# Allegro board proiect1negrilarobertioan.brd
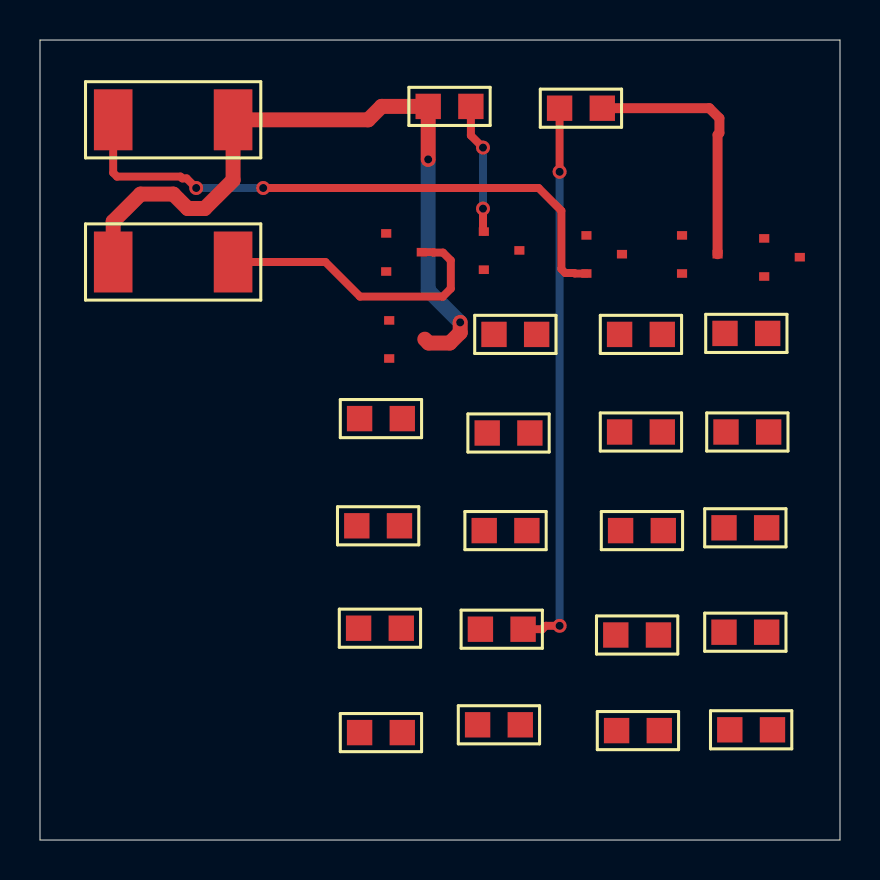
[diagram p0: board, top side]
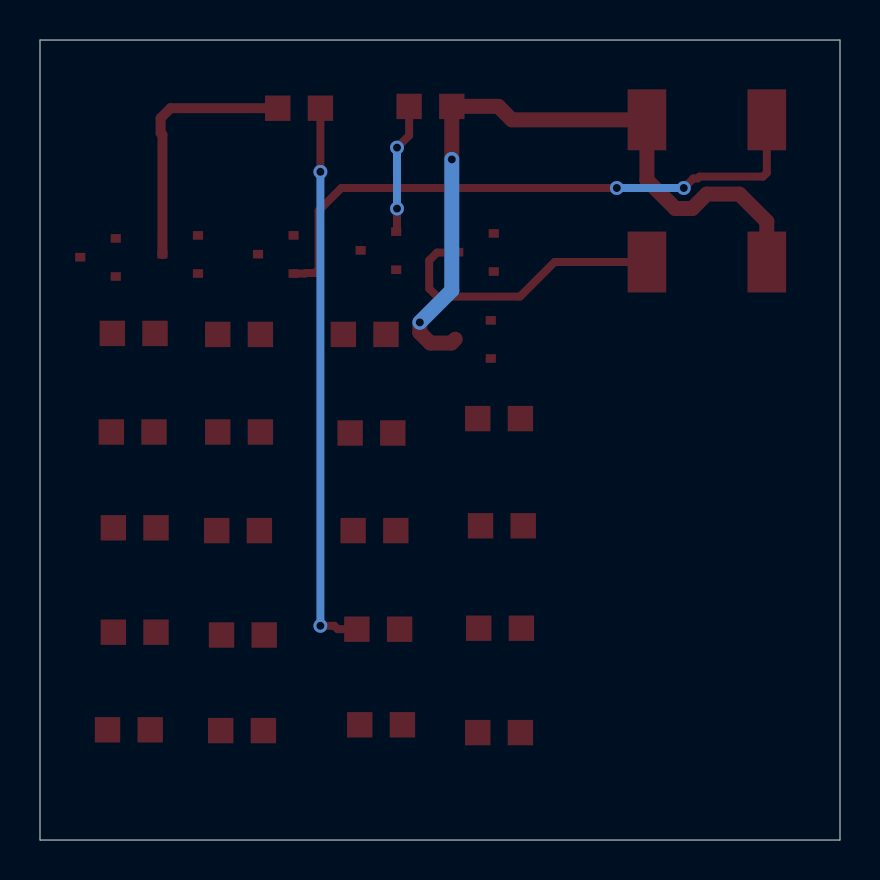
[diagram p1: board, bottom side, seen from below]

Outline 40 x 40 mm; copper layers: TOP, BOTTOM. Coordinates in mm from the lower left corner of the outline.
Outline path: 0,40 0,0 40,0 40,40 0,40

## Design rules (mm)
nets with their own width: min track width 0.4; nets N08480 N08488 N08492 N08504 N08580 N08628 N08668 N08672 N08736 N08748 N08902 N08906 N09206 N09477 N09479 N087941 N089761 N090261
nets with their own width: min track width 0.5; nets VIN VOUT
nets with their own width: min track width 0.75; nets GND

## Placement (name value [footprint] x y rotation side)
C1  1n  [SMC0805]  19.41 36.68 0 top
C2  1n  [SMC0805]  25.98 36.59 0 top
J1  CON2  [SMR2512]  3.66 36.01 0 top
J2  CON2  [SMR2512]  3.66 28.9 0 top
Q1  BC856B  [SOT23]  18.2 29.39 0 top
Q2  BC856B  [SOT23]  23.08 29.48 0 top
Q3  BC856B  [SOT23]  28.21 29.29 0 top
Q4  BC856B  [SOT23]  32.99 29.29 0 top
Q5  BC846B  [SOT23]  37.1 29.14 0 top
Q6  BC856B  [SOT23]  18.35 25.04 0 top
R1  15k  [SMR0805]  22.7 25.28 0 top
R2  820  [SMR0805]  22.36 20.35 0 top
R3  15k  [SMR0805]  22.21 15.47 0 top
R4  820  [SMR0805]  22.02 10.54 0 top
R5  100k  [SMR0805]  21.88 5.76 0 top
R6  33  [SMR0805]  28.98 25.28 0 top
R8  100  [SMR0805]  28.98 20.4 0 top
R9  150  [SMR0805]  29.03 15.47 0 top
R10  150  [SMR0805]  28.79 10.25 0 top
R11  10  [SMR0805]  28.83 5.47 0 top
R12  150  [SMR0805]  34.25 25.33 0 top
R13  33  [SMR0805]  34.3 20.4 0 top
R14  150  [SMR0805]  34.2 15.61 0 top
R15  150  [SMR0805]  34.2 10.39 0 top
R16  150  [SMR0805]  34.49 5.51 0 top
R17  10k  [SMR0805]  15.98 21.07 0 top
R18  470  [SMR0805]  15.84 15.71 0 top
R19  15k  [SMR0805]  15.93 10.59 0 top
R20  510  [SMR0805]  15.98 5.37 0 top

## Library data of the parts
C1 C2 = C
J1 J2 = CON2
Q1-Q4 Q6 = BC856B
Q5 = BC846B
R1-R6 R8-R20 = R

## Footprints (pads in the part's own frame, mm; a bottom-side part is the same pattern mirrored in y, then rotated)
SMC0805
  rect 1.27x1.27 smd: 1(0,0) 2(2.134,0)
SMR0805
  rect 1.27x1.27 smd: 1(0,0) 2(2.134,0)
SMR2512
  rect 1.93x3.048 smd: 1(0,0) 2(5.994,0)
SOT23
  rect 0.508x0.432 smd: 1(-0.889,0.94) 2(-0.889,-0.965) 3(0.889,0)

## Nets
GND: C1.1 J1.2 J2.1 Q6.3 R1.1 R6.1
VIN: Q1.1 R5.2 R17.1 R19.2
VOUT: C2.2 Q4.3 Q5.3 R17.2 R18.2
N08480: C1.2 Q2.1 R2.2 R3.1
N08488: R3.2 R4.1
N08492: C2.1 R4.2
N08504: J1.1 Q3.2(E) R9.2 R16.2
N08580: R9.1 R14.2
N08628: R15.2 R16.1
N08668: R8.2 R14.1
N08672: R1.2 R2.1
N08736: Q3.1 Q3.3 Q4.1 Q4.2(E) R12.2 R15.1
N08748: Q1.2(E) Q2.2(E) R8.1
N08902: Q2.3 Q5.1 R10.2
N08906: J2.2 Q1.3 Q5.2(E) R11.1 R13.1
N09206: Q6.1 R5.1
N09477: R19.1 R20.2
N09479: Q6.2(E) R20.1
N087941: R6.2 R18.1
N089761: R12.1 R13.2
N090261: R10.1 R11.2

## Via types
v1: diameter 0.7, hole 0.4, TOP to BOTTOM, 8 vias

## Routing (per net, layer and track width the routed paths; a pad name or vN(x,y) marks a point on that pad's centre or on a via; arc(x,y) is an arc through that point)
GND: length 36.6
  TOP w0.75: v1(19.41,34.03) C1.1 17.08,36.68 16.41,36.01 J1.2 9.65,32.99 8.23,31.57 7.39,31.57 6.67,32.29 5.03,32.29 3.66,30.93 J2.1 ; v1(21.01,25.88) 21.01,25.37 20.49,24.85 19.43,24.85 Q6.3
  BOTTOM w0.75: v1(19.41,34.03) 19.41,27.48 v1(21.01,25.88)
VOUT: length 12.9
  TOP w0.5: C2.2 33.47,36.59 33.97,36.09 33.97,35.35 33.88,35.26 Q4.3
N08480: length 6.5
  TOP w0.4: C1.2 21.54,35.23 v1(22.15,34.62) ; v1(22.15,31.57) 22.15,30.46 Q2.1
  BOTTOM w0.4: v1(22.15,34.62) v1(22.15,31.57)
N08492: length 27.8
  TOP w0.4: R4.2 25.12,10.54 25.29,10.71 v1(25.98,10.71) ; C2.1 v1(25.98,33.41)
  BOTTOM w0.4: v1(25.98,33.41) v1(25.98,10.71)
N08504: length 30.1
  TOP w0.4: v1(7.81,32.6) 7.33,33.08 7.12,33.08 7.03,33.17 3.85,33.17 3.66,33.36 J1.1 ; v1(11.16,32.6) 24.93,32.6 26.07,31.46 26.07,28.54 26.26,28.35 26.71,28.35 26.74,28.32 Q3.2
  BOTTOM w0.4: v1(7.81,32.6) v1(11.16,32.6)
N08906: length 14.8
  TOP w0.4: Q1.3 19.67,29.39 19.69,29.37 20.15,29.37 20.54,28.98 20.54,27.57 20.14,27.17 16,27.17 14.27,28.9 J2.2

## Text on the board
Ref Des/Assembly Top: Negrila Robert | 432 C | PDCE 1 2022-2023
